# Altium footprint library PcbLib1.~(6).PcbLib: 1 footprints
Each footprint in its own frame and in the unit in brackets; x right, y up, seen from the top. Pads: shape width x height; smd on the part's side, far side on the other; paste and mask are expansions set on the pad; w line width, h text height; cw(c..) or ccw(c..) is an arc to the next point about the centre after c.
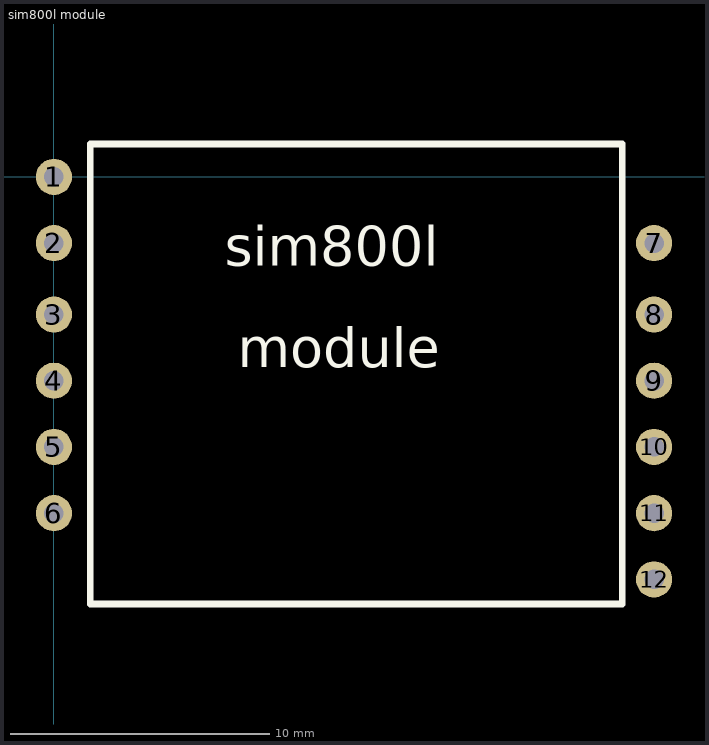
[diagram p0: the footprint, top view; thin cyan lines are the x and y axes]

## sim800l module [mm]
height 10
pads (12):
  round 1.4 hole 0.75: 1(0,0) 2(0,-2.56) 3(0,-5.32) 4(0,-7.88) 5(0,-10.44) 6(0,-13) 7(23.2,-2.56) 8(23.2,-5.32) 9(23.2,-7.88) 10(23.2,-10.44) 11(23.2,-13) 12(23.2,-15.56)
Top Overlay:
  lines w0.254: 1.397,-16.51 1.397,1.27 19.939,1.27 21.971,1.27 21.971,-16.51 1.397,-16.51
  text "sim800l" at 6.604,-3.429 h1.52
  text "module" at 7.112,-7.366 h1.52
